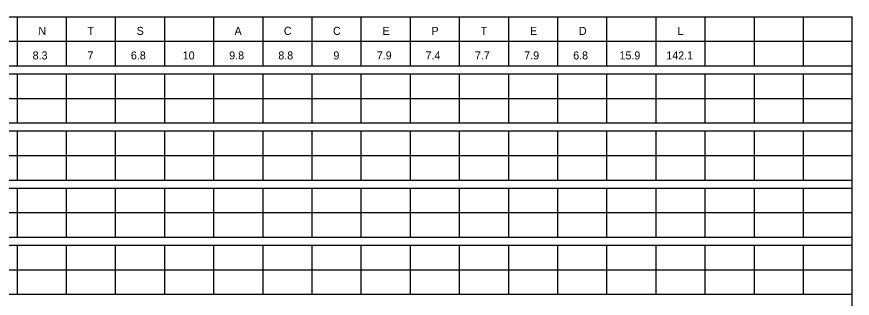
# Model space of a CAD drawing. Extents: x 17890459 to 17890580, y 17897938 to 17898017.
# Drawn here: x 17890480.8 to 17890519.19, y 17897978.61 to 17897991.54 of the extents above; entities that cross this region are included whole.
import ezdxf

# ---------------------------------------------------------------- set-up
doc = ezdxf.new("R2010")
doc.units = 0
doc.layers.add('GSSign', color=7, linetype='Continuous')
doc.layers.add('SheetLinesMisc2_dp', color=7, linetype='Continuous')

msp = doc.modelspace()

# ---------------------------------------------------------------- linework, layer by layer
at = {"layer": 'SheetLinesMisc2_dp'}
for p, q in [((17890463.699, 17897991.536), (17890519.188, 17897991.536)), ((17890480.815, 17897991.536), (17890480.815, 17897989.281)), ((17890483.072, 17897991.536), (17890483.072, 17897989.281)), ((17890485.329, 17897991.536), (17890485.329, 17897989.281)), ((17890487.586, 17897991.536), (17890487.586, 17897989.281)), ((17890489.844, 17897991.536), (17890489.844, 17897989.281)), ((17890492.101, 17897991.536), (17890492.101, 17897989.281)), ((17890494.358, 17897991.536), (17890494.358, 17897989.281)), ((17890496.615, 17897991.536), (17890496.615, 17897989.281)), ((17890498.873, 17897991.536), (17890498.873, 17897989.281)), ((17890501.13, 17897991.536), (17890501.13, 17897989.281)), ((17890503.387, 17897991.536), (17890503.387, 17897989.281)), ((17890505.644, 17897991.536), (17890505.644, 17897989.281)), ((17890507.902, 17897991.536), (17890507.902, 17897989.281)), ((17890510.159, 17897991.536), (17890510.159, 17897989.281)), ((17890512.416, 17897991.536), (17890512.416, 17897989.281)), ((17890514.673, 17897991.536), (17890514.673, 17897989.281)), ((17890516.931, 17897991.536), (17890516.931, 17897989.281)), ((17890519.188, 17897947.331), (17890519.188, 17897991.536)), ((17890463.699, 17897990.408), (17890519.188, 17897990.408)), ((17890463.699, 17897989.281), (17890519.188, 17897989.281)), ((17890463.699, 17897988.914), (17890519.188, 17897988.914)), ((17890480.815, 17897988.914), (17890480.815, 17897986.659)), ((17890483.072, 17897988.914), (17890483.072, 17897986.659)), ((17890485.329, 17897988.914), (17890485.329, 17897986.659)), ((17890487.586, 17897988.914), (17890487.586, 17897986.659)), ((17890489.844, 17897988.914), (17890489.844, 17897986.659)), ((17890492.101, 17897988.914), (17890492.101, 17897986.659)), ((17890494.358, 17897988.914), (17890494.358, 17897986.659)), ((17890496.615, 17897988.914), (17890496.615, 17897986.659)), ((17890498.873, 17897988.914), (17890498.873, 17897986.659)), ((17890501.13, 17897988.914), (17890501.13, 17897986.659)), ((17890503.387, 17897988.914), (17890503.387, 17897986.659)), ((17890505.644, 17897988.914), (17890505.644, 17897986.659)), ((17890507.902, 17897988.914), (17890507.902, 17897986.659)), ((17890510.159, 17897988.914), (17890510.159, 17897986.659)), ((17890512.416, 17897988.914), (17890512.416, 17897986.659)), ((17890514.673, 17897988.914), (17890514.673, 17897986.659)), ((17890516.931, 17897988.914), (17890516.931, 17897986.659)), ((17890463.699, 17897987.786), (17890519.188, 17897987.786)), ((17890463.699, 17897986.659), (17890519.188, 17897986.659)), ((17890463.699, 17897986.291), (17890519.188, 17897986.291)), ((17890480.815, 17897986.291), (17890480.815, 17897984.037)), ((17890483.072, 17897986.291), (17890483.072, 17897984.037)), ((17890485.329, 17897986.291), (17890485.329, 17897984.037)), ((17890487.586, 17897986.291), (17890487.586, 17897984.037)), ((17890489.844, 17897986.291), (17890489.844, 17897984.037)), ((17890492.101, 17897986.291), (17890492.101, 17897984.037)), ((17890494.358, 17897986.291), (17890494.358, 17897984.037)), ((17890496.615, 17897986.291), (17890496.615, 17897984.037)), ((17890498.873, 17897986.291), (17890498.873, 17897984.037)), ((17890501.13, 17897986.291), (17890501.13, 17897984.037)), ((17890503.387, 17897986.291), (17890503.387, 17897984.037)), ((17890505.644, 17897986.291), (17890505.644, 17897984.037)), ((17890507.902, 17897986.291), (17890507.902, 17897984.037)), ((17890510.159, 17897986.291), (17890510.159, 17897984.037)), ((17890512.416, 17897986.291), (17890512.416, 17897984.037)), ((17890514.673, 17897986.291), (17890514.673, 17897984.037)), ((17890516.931, 17897986.291), (17890516.931, 17897984.037)), ((17890463.699, 17897985.165), (17890519.188, 17897985.165)), ((17890463.699, 17897984.037), (17890519.188, 17897984.037)), ((17890463.699, 17897983.669), (17890519.188, 17897983.669)), ((17890480.815, 17897983.669), (17890480.815, 17897981.415)), ((17890483.072, 17897983.669), (17890483.072, 17897981.415)), ((17890485.329, 17897983.669), (17890485.329, 17897981.415)), ((17890487.586, 17897983.669), (17890487.586, 17897981.415)), ((17890489.844, 17897983.669), (17890489.844, 17897981.415)), ((17890492.101, 17897983.669), (17890492.101, 17897981.415)), ((17890494.358, 17897983.669), (17890494.358, 17897981.415)), ((17890496.615, 17897983.669), (17890496.615, 17897981.415)), ((17890498.873, 17897983.669), (17890498.873, 17897981.415)), ((17890501.13, 17897983.669), (17890501.13, 17897981.415)), ((17890503.387, 17897983.669), (17890503.387, 17897981.415)), ((17890505.644, 17897983.669), (17890505.644, 17897981.415)), ((17890507.902, 17897983.669), (17890507.902, 17897981.415)), ((17890510.159, 17897983.669), (17890510.159, 17897981.415)), ((17890512.416, 17897983.669), (17890512.416, 17897981.415)), ((17890514.673, 17897983.669), (17890514.673, 17897981.415)), ((17890516.931, 17897983.669), (17890516.931, 17897981.415)), ((17890463.699, 17897982.543), (17890519.188, 17897982.543)), ((17890463.699, 17897981.415), (17890519.188, 17897981.415)), ((17890463.699, 17897981.048), (17890519.188, 17897981.048)), ((17890480.815, 17897981.048), (17890480.815, 17897978.794)), ((17890483.072, 17897981.048), (17890483.072, 17897978.794)), ((17890485.329, 17897981.048), (17890485.329, 17897978.794)), ((17890487.586, 17897981.048), (17890487.586, 17897978.794)), ((17890489.844, 17897981.048), (17890489.844, 17897978.794)), ((17890492.101, 17897981.048), (17890492.101, 17897978.794)), ((17890494.358, 17897981.048), (17890494.358, 17897978.794)), ((17890496.615, 17897981.048), (17890496.615, 17897978.794)), ((17890498.873, 17897981.048), (17890498.873, 17897978.794)), ((17890501.13, 17897981.048), (17890501.13, 17897978.794)), ((17890503.387, 17897981.048), (17890503.387, 17897978.794)), ((17890505.644, 17897981.048), (17890505.644, 17897978.794)), ((17890507.902, 17897981.048), (17890507.902, 17897978.794)), ((17890510.159, 17897981.048), (17890510.159, 17897978.794)), ((17890512.416, 17897981.048), (17890512.416, 17897978.794)), ((17890514.673, 17897981.048), (17890514.673, 17897978.794)), ((17890516.931, 17897981.048), (17890516.931, 17897978.794)), ((17890463.699, 17897979.92), (17890519.188, 17897979.921)), ((17890463.699, 17897978.794), (17890519.188, 17897978.794))]:
    msp.add_line(p, q, dxfattribs=at)

# ---------------------------------------------------------------- texts
at = {"layer": 'GSSign'}
for s, height, p in [('N', 0.368, (17890481.792, 17897990.702)), ('N', 0.368, (17890481.792, 17897990.702)), ('T', 0.368, (17890484.05, 17897990.702)), ('T', 0.368, (17890484.05, 17897990.702)), ('S', 0.368, (17890486.308, 17897990.702)), ('S', 0.368, (17890486.308, 17897990.702)), ('A', 0.368, (17890490.806, 17897990.702)), ('A', 0.368, (17890490.806, 17897990.702)), ('C', 0.368, (17890493.072, 17897990.702)), ('C', 0.368, (17890493.072, 17897990.702)), ('C', 0.368, (17890495.33, 17897990.702)), ('C', 0.368, (17890495.33, 17897990.702)), ('E', 0.368, (17890497.605, 17897990.702)), ('E', 0.368, (17890497.605, 17897990.702)), ('P', 0.368, (17890499.854, 17897990.702)), ('P', 0.368, (17890499.854, 17897990.702)), ('T', 0.368, (17890502.112, 17897990.702)), ('T', 0.368, (17890502.112, 17897990.702)), ('E', 0.368, (17890504.379, 17897990.702)), ('E', 0.368, (17890504.379, 17897990.702)), ('D', 0.368, (17890506.628, 17897990.702)), ('D', 0.368, (17890506.628, 17897990.702)), ('L', 0.368, (17890511.161, 17897990.702)), ('L', 0.368, (17890511.161, 17897990.702)), ('8.3', 0.3676, (17890481.53, 17897989.575)), ('8.3', 0.3676, (17890481.53, 17897989.575)), ('7', 0.368, (17890484.05, 17897989.575)), ('7', 0.368, (17890484.05, 17897989.575)), ('6.8', 0.3676, (17890486.045, 17897989.575)), ('6.8', 0.3676, (17890486.045, 17897989.575)), ('10', 0.3676, (17890488.425, 17897989.575)), ('10', 0.3676, (17890488.425, 17897989.575)), ('9.8', 0.3676, (17890490.561, 17897989.575)), ('9.8', 0.3676, (17890490.561, 17897989.575)), ('8.8', 0.3676, (17890492.818, 17897989.575)), ('8.8', 0.3676, (17890492.818, 17897989.575)), ('9', 0.368, (17890495.348, 17897989.575)), ('9', 0.368, (17890495.348, 17897989.575)), ('7.9', 0.3676, (17890497.343, 17897989.575)), ('7.9', 0.3676, (17890497.343, 17897989.575)), ('7.4', 0.3676, (17890499.583, 17897989.575)), ('7.4', 0.3676, (17890499.583, 17897989.575)), ('7.7', 0.3676, (17890501.85, 17897989.575)), ('7.7', 0.3676, (17890501.85, 17897989.575)), ('7.9', 0.3676, (17890504.116, 17897989.575)), ('7.9', 0.3676, (17890504.116, 17897989.575)), ('6.8', 0.3676, (17890506.365, 17897989.575)), ('6.8', 0.3676, (17890506.365, 17897989.575)), ('15.9', 0.3676, (17890508.492, 17897989.575)), ('15.9', 0.3676, (17890508.492, 17897989.575)), ('142.1', 0.3676, (17890510.644, 17897989.575)), ('142.1', 0.3676, (17890510.644, 17897989.575))]:
    msp.add_text(s, height=height, dxfattribs=at).set_placement(p)

doc.saveas('drawing.dxf')
